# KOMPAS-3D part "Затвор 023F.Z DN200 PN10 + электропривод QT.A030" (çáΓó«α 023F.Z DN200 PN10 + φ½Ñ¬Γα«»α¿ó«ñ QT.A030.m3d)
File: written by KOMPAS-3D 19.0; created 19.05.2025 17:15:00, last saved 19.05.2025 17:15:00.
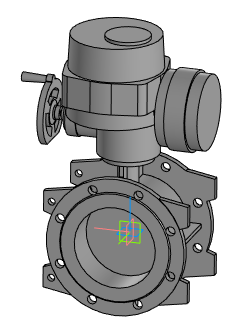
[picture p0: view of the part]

Document properties: Полное имя файла: Затвор 023F.Z DN200 PN10 + электропривод.a3d

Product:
- Part/product: Затвор 023F.Z DN200 PN10 + электропривод QT.A030
    Масса: 156.245

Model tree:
1. Операция без истории:1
